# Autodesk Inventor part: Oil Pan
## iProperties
Shininess: 25.0
Length Units: 11272
Angle Units: 11279
Time Units: 11290
Mass Units: 11286
Length Display Precision: 3
Angle Display Precision: 2
Compacted: True
Manager: Lebovitz
Company: Autodesk
Created: 2000-11
Part Number: Oil Pan
Document SubType Name: Modeling
Designer: The PD team
Project: Inventor Samples
Density: 0.0
Volumn: 0.0
Area: 0.0
PropertySet Name: Model Information
Control State: 0
Master: False
Checked Out: False
Author: The PD Team
Revision Number: A
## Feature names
1. Extrusion1
2. Extrusion2
3. FaceDraft1
4. Split1
5. FaceDraft5
6. FaceDraft4
7. FaceDraft7
8. Fillet4
9. Fillet1
10. Fillet2
11. Shell1
12. Extrusion6
13. Mirror1
14. Extrusion7
15. Mirror2
16. Shell4
17. Fillet10
18. Hole1
19. Fillet11
20. Fillet12
21. Extrusion8
22. Fillet13
23. Hole2
